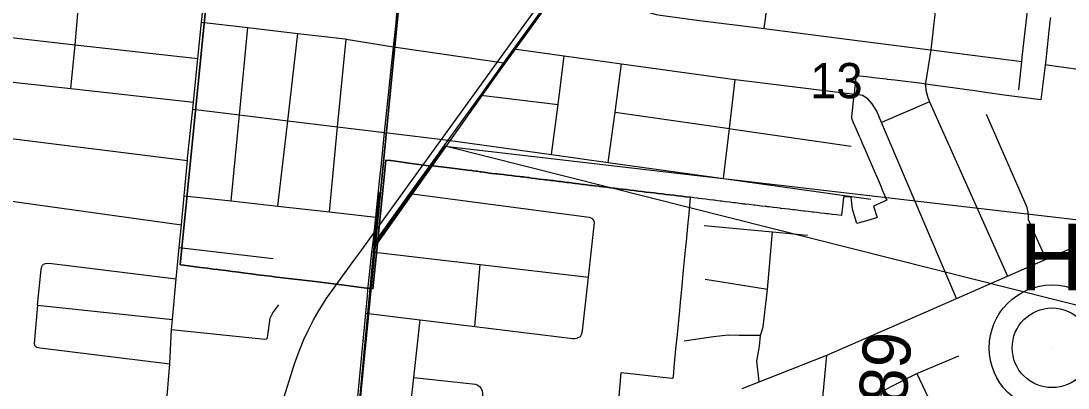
# Model space of a CAD drawing. Extents: x 0 to 34, y -3.9 to 26.2.
# Drawn here: x 5.478 to 6.718, y 17.116 to 17.55 of the extents above; entities that cross this region are included whole.
import ezdxf

# ---------------------------------------------------------------- set-up
doc = ezdxf.new("R2010")
doc.units = 0
for name, color, linetype in [('GM_X_City_Street', 7, 'Continuous'), ('GM_X_Corporation', 7, 'Continuous'), ('GM_X_County_Road', 7, 'Continuous'), ('GM_X_County_Road_Text', 7, 'Continuous'), ('GM_X_Rail_Line', 7, 'Continuous'), ('GM_X_Section', 7, 'Continuous'), ('GM_X_Section_Text', 7, 'Continuous'), ('GM_X_State_Route', 7, 'Continuous'), ('GM_X_Township_Road', 7, 'Continuous'), ('GM_X_Unincorporated', 7, 'Continuous'), ('GM_X_Unincorporated_Location', 7, 'Continuous'), ('GM_X_Unincorporated_Text', 7, 'Continuous'), ('GM_X_US_Route', 7, 'Continuous'), ('SH_Text', 7, 'Continuous')]:
    doc.layers.add(name, color=color, linetype=linetype)

msp = doc.modelspace()

# ---------------------------------------------------------------- linework, layer by layer
at = {"layer": 'GM_X_City_Street'}
for p, q in [((6.0224, 17.4626), (6.1139, 17.4515)), ((5.6654, 17.282), (5.7766, 17.2692)), ((6.0155, 17.1885), (6.0217, 17.262)), ((5.4976, 17.2137), (5.6574, 17.1968))]:
    msp.add_line(p, q, dxfattribs=at)
for points in [[(6.3581, 17.5413), (6.367, 17.6089), (6.3745, 17.666), (6.3821, 17.7239)], [(6.6593, 17.4687), (6.663, 17.5023), (6.6636, 17.5075), (6.6701, 17.5656), (6.6704, 17.569), (6.6767, 17.6249), (6.6834, 17.6857), (6.6862, 17.7111)], [(6.549, 17.4743), (6.5555, 17.5161), (6.5632, 17.5831), (6.5696, 17.6395), (6.5764, 17.6991)], [(6.1086, 17.5816), (6.1848, 17.571), (6.1972, 17.568), (6.23, 17.558), (6.2379, 17.5567), (6.2754, 17.5519), (6.3581, 17.5413), (6.4712, 17.5269), (6.5519, 17.5165), (6.5555, 17.5161), (6.663, 17.5023)], [(5.5372, 17.4703), (5.542, 17.5223), (5.5459, 17.5641), (5.5475, 17.5686)], [(5.6971, 16.9593), (5.6819, 16.9939), (5.647, 17.0778), (5.6493, 17.0824), (5.6542, 17.1442), (5.6563, 17.1848), (5.6574, 17.1968), (5.6619, 17.245), (5.6654, 17.282), (5.668, 17.309), (5.6712, 17.3434), (5.6751, 17.3852), (5.6753, 17.3877), (5.6813, 17.4458), (5.6821, 17.4541), (5.6874, 17.5058), (5.6919, 17.549), (5.6925, 17.5555), (5.6935, 17.5648)], [(5.6919, 17.549), (5.7464, 17.5426), (5.8059, 17.5357), (5.8617, 17.5292), (5.8629, 17.529), (5.9191, 17.5198), (5.9275, 17.5186), (6.0498, 17.5008)], [(5.4246, 17.5356), (5.542, 17.5223), (5.6874, 17.5058)], [(5.727, 17.3372), (5.7366, 17.4391), (5.7464, 17.5426)], [(5.7823, 17.331), (5.794, 17.4321), (5.8059, 17.5357)], [(5.8433, 17.3242), (5.8529, 17.425), (5.8629, 17.529)], [(6.0617, 17.5173), (6.1213, 17.509), (6.1892, 17.4997), (6.3237, 17.4811), (6.327, 17.4807), (6.4649, 17.4638)], [(6.1063, 17.3921), (6.1139, 17.4515), (6.1213, 17.509)], [(6.1732, 17.3827), (6.1814, 17.4425), (6.1892, 17.4997)], [(5.4395, 17.4812), (5.5372, 17.4703), (5.6821, 17.4541)], [(6.3099, 17.3637), (6.3169, 17.423), (6.3237, 17.4811)], [(5.6813, 17.4458), (5.7366, 17.4391), (5.794, 17.4321), (5.8529, 17.425), (5.9085, 17.4182), (5.9125, 17.4178), (5.9838, 17.4091), (6.1063, 17.3921), (6.1732, 17.3827), (6.3099, 17.3637), (6.4842, 17.3394)], [(6.1814, 17.4425), (6.3169, 17.423), (6.3211, 17.4224), (6.4608, 17.4023)], [(5.4401, 17.3772), (5.4428, 17.4045), (5.4444, 17.407), (5.4464, 17.4092), (5.4488, 17.4101), (5.4528, 17.4111), (5.4567, 17.412), (5.46, 17.4118), (5.6751, 17.3852)], [(5.4401, 17.3772), (5.4389, 17.3468), (5.4393, 17.3451), (5.4401, 17.3443), (5.4433, 17.3427), (5.4506, 17.3402), (5.4612, 17.3377), (5.668, 17.309)], [(5.9384, 17.3461), (6.1506, 17.3179), (6.154, 17.3167)], [(5.6712, 17.3434), (5.727, 17.3372), (5.7823, 17.331), (5.8433, 17.3242), (5.898, 17.3181)], [(6.1404, 17.1765), (6.1418, 17.1792), (6.1428, 17.1833), (6.1498, 17.2469), (6.1569, 17.3117), (6.1563, 17.3141), (6.1554, 17.3154), (6.154, 17.3167)], [(5.8936, 17.277), (6.0217, 17.262), (6.1498, 17.2469)], [(5.4976, 17.2137), (5.5017, 17.2561), (5.5027, 17.2597), (5.5035, 17.2612), (5.5048, 17.2625), (5.507, 17.2632), (5.5098, 17.2634), (5.5147, 17.2631), (5.6619, 17.245)], [(5.4976, 17.2137), (5.4937, 17.1682), (5.4941, 17.1665), (5.4954, 17.1649), (5.4968, 17.1642), (5.5004, 17.1633), (5.5037, 17.1627), (5.6542, 17.1442)], [(5.6563, 17.1848), (5.7669, 17.1737), (5.7685, 17.1739), (5.7692, 17.1741), (5.7697, 17.1746), (5.77, 17.1754), (5.7704, 17.1779), (5.7729, 17.1983), (5.7761, 17.2047), (5.7834, 17.2141)], [(5.8862, 17.2044), (5.9472, 17.1969), (5.9508, 17.1965), (6.0155, 17.1885), (6.1314, 17.1743), (6.1336, 17.1743), (6.1368, 17.175), (6.1404, 17.1765)], [(5.9329, 17.0358), (5.9332, 17.0387), (5.9432, 17.1282), (5.9508, 17.1965)], [(5.9432, 17.1282), (6.0162, 17.1201), (6.0188, 17.1189), (6.0207, 17.1174), (6.023, 17.1151), (6.0241, 17.1123), (6.0246, 17.1089), (6.0243, 17.1052), (6.0187, 17.0469)]]:
    msp.add_lwpolyline(points, dxfattribs=at)
at = {"layer": 'GM_X_Corporation'}
for points in [[(5.6984, 17.5835), (5.6666, 17.2614), (5.6707, 17.261), (5.6731, 17.2607), (5.6907, 17.2585), (5.6983, 17.2575), (5.7057, 17.2566), (5.711, 17.2559), (5.7133, 17.2556), (5.7207, 17.2547), (5.7283, 17.2537), (5.7358, 17.2527), (5.7433, 17.2518), (5.7508, 17.2508), (5.7584, 17.2499), (5.7614, 17.2495), (5.7658, 17.2489), (5.7734, 17.248), (5.7779, 17.2474), (5.7808, 17.2471), (5.7984, 17.245), (5.8264, 17.2418), (5.8447, 17.2394), (5.8576, 17.2379), (5.8869, 17.2341), (5.8885, 17.2339), (5.8944, 17.2332), (5.8992, 17.2785), (5.9101, 17.3857), (5.9149, 17.3851), (5.9158, 17.385), (5.9431, 17.3811), (5.9463, 17.3806), (5.9491, 17.3803), (5.9577, 17.3792), (5.9605, 17.3789), (5.9688, 17.3784), (5.9854, 17.3764), (5.9947, 17.3752), (6.0041, 17.374), (6.0071, 17.3737), (6.0119, 17.3731), (6.0135, 17.3729), (6.0165, 17.3725), (6.0187, 17.3723), (6.0212, 17.3719), (6.023, 17.3717), (6.026, 17.3712), (6.0307, 17.3704), (6.0323, 17.3703), (6.0354, 17.3699), (6.0401, 17.3694), (6.0418, 17.3692), (6.0447, 17.3689), (6.0495, 17.3684), (6.0512, 17.3682), (6.0539, 17.3679), (6.0587, 17.3673), (6.0606, 17.3671), (6.0636, 17.3667), (6.0682, 17.3661), (6.0699, 17.3659), (6.0728, 17.3656), (6.0775, 17.365), (6.0793, 17.3648), (6.082, 17.3644), (6.0869, 17.3638), (6.0887, 17.3636), (6.0916, 17.3632), (6.0963, 17.3627), (6.0982, 17.3624), (6.1009, 17.3621), (6.1056, 17.3615), (6.1076, 17.3613), (6.1104, 17.3609), (6.115, 17.3604), (6.117, 17.3602), (6.1197, 17.3598), (6.1243, 17.3592), (6.1265, 17.359), (6.1293, 17.3586), (6.1315, 17.3584), (6.134, 17.358), (6.1358, 17.3578), (6.1384, 17.3575), (6.1432, 17.3569), (6.1452, 17.3567), (6.148, 17.3563), (6.1526, 17.3557), (6.1546, 17.3555), (6.1573, 17.3552), (6.162, 17.3546), (6.1628, 17.3545), (6.1669, 17.354), (6.1713, 17.3534), (6.1738, 17.3531), (6.176, 17.3529), (6.1808, 17.3523), (6.1837, 17.3519), (6.1854, 17.3517), (6.1901, 17.3511), (6.1948, 17.3506), (6.1994, 17.35), (6.2041, 17.3495), (6.2089, 17.3489), (6.2135, 17.3484), (6.2182, 17.3478), (6.2229, 17.3473), (6.2277, 17.3467), (6.2323, 17.3461), (6.237, 17.3456), (6.2417, 17.345), (6.2464, 17.3445), (6.2511, 17.3439), (6.2558, 17.3433), (6.2604, 17.3428), (6.2651, 17.3422), (6.2699, 17.3417), (6.2705, 17.3416), (6.2682, 17.3175), (6.268, 17.3154), (6.2659, 17.2943), (6.2658, 17.2931), (6.2645, 17.279), (6.2622, 17.2553), (6.2599, 17.2323), (6.2585, 17.2174), (6.2575, 17.2074), (6.2544, 17.1751), (6.2535, 17.1659), (6.251, 17.1404), (6.2504, 17.1336), (6.2497, 17.127), (6.2416, 17.1278), (6.2207, 17.1302), (6.2069, 17.1317), (6.1881, 17.1338), (6.1833, 17.0778)], [(6.6968, 17.5547), (6.6962, 17.5496), (6.6958, 17.5453), (6.6954, 17.542), (6.6951, 17.539), (6.6947, 17.5352), (6.6946, 17.5348), (6.6938, 17.5272), (6.693, 17.5195), (6.6921, 17.512), (6.6913, 17.5041), (6.6902, 17.4948), (6.689, 17.4853), (6.6879, 17.4759), (6.6868, 17.4666), (6.6856, 17.4569), (6.6639, 17.4598), (6.6544, 17.461), (6.6422, 17.4626), (6.6254, 17.465), (6.6046, 17.468), (6.601, 17.4685), (6.5815, 17.4711), (6.5546, 17.4746), (6.5447, 17.4763), (6.5127, 17.4801), (6.5041, 17.4811), (6.5029, 17.4813), (6.487, 17.4831), (6.4854, 17.4833), (6.4751, 17.4846), (6.4666, 17.4856), (6.4664, 17.4856), (6.4663, 17.4844), (6.4647, 17.4684), (6.4647, 17.4682), (6.4637, 17.4588), (6.4615, 17.4373), (6.4613, 17.4352), (6.4635, 17.4303), (6.467, 17.4221), (6.4705, 17.4139), (6.4722, 17.4099), (6.474, 17.4057), (6.4759, 17.4014), (6.4775, 17.3976), (6.481, 17.3894), (6.4846, 17.3812), (6.4881, 17.373), (6.4882, 17.3727), (6.4916, 17.3649), (6.4951, 17.3567), (6.4986, 17.3486), (6.4986, 17.3485), (6.4994, 17.3468), (6.5025, 17.3395), (6.5031, 17.3381), (6.4874, 17.3311), (6.4874, 17.3309), (6.4917, 17.3175), (6.4807, 17.3142), (6.4732, 17.312), (6.4676, 17.3104), (6.4626, 17.3274), (6.4611, 17.3416), (6.4519, 17.3421), (6.4517, 17.3421), (6.4505, 17.3298), (6.4496, 17.3211), (6.4495, 17.32), (6.4436, 17.3207), (6.4389, 17.3213), (6.4341, 17.3218), (6.4319, 17.3221), (6.4295, 17.3224), (6.4248, 17.3229), (6.4201, 17.3235), (6.4165, 17.3239), (6.4153, 17.3241), (6.4146, 17.3241), (6.4106, 17.3246), (6.4061, 17.3252), (6.4049, 17.3253), (6.4013, 17.3257), (6.3965, 17.3262), (6.394, 17.3265), (6.3918, 17.3268), (6.3871, 17.3273), (6.3825, 17.3279), (6.3777, 17.3284), (6.377, 17.3285), (6.3732, 17.329), (6.3685, 17.3295), (6.3639, 17.3301), (6.3619, 17.3303), (6.3609, 17.3305), (6.359, 17.3306), (6.3543, 17.3312), (6.3498, 17.3317), (6.3464, 17.3322), (6.3452, 17.3323), (6.3402, 17.3329), (6.3357, 17.3334), (6.3339, 17.3336), (6.3326, 17.3338), (6.331, 17.3339), (6.3262, 17.3345), (6.3237, 17.3348), (6.3216, 17.3351), (6.3194, 17.3354), (6.3168, 17.3357), (6.3122, 17.3363), (6.3074, 17.3369), (6.3058, 17.3371), (6.3028, 17.3375), (6.3008, 17.3377), (6.2989, 17.338), (6.2981, 17.3381), (6.2932, 17.3387), (6.2888, 17.3393), (6.284, 17.3399), (6.2803, 17.3403), (6.2793, 17.3405), (6.2746, 17.3411), (6.2731, 17.3413), (6.2705, 17.3416), (6.2699, 17.3417), (6.2651, 17.3422), (6.2604, 17.3428), (6.2558, 17.3433), (6.2511, 17.3439), (6.2464, 17.3445), (6.2417, 17.345), (6.237, 17.3456), (6.2323, 17.3461), (6.2277, 17.3467), (6.2229, 17.3473), (6.2182, 17.3478), (6.2135, 17.3484), (6.2089, 17.3489), (6.2041, 17.3495), (6.1994, 17.35), (6.1948, 17.3506), (6.1901, 17.3511), (6.1854, 17.3517), (6.1837, 17.3519), (6.1808, 17.3523), (6.176, 17.3529), (6.1738, 17.3531), (6.1713, 17.3534), (6.1669, 17.354), (6.1628, 17.3545), (6.162, 17.3546), (6.1573, 17.3552), (6.1546, 17.3555), (6.1526, 17.3557), (6.148, 17.3563), (6.1452, 17.3567), (6.1432, 17.3569), (6.1384, 17.3575), (6.1358, 17.3578), (6.134, 17.358), (6.1293, 17.3586), (6.1265, 17.359), (6.1243, 17.3592), (6.1197, 17.3598), (6.117, 17.3602), (6.115, 17.3604), (6.1104, 17.3609), (6.1076, 17.3613), (6.1056, 17.3615), (6.1009, 17.3621), (6.0982, 17.3624), (6.0963, 17.3627), (6.0916, 17.3632), (6.0887, 17.3636), (6.0869, 17.3638), (6.082, 17.3644), (6.0793, 17.3648), (6.0775, 17.365), (6.0728, 17.3656), (6.0699, 17.3659), (6.0682, 17.3661), (6.0636, 17.3667), (6.0606, 17.3671), (6.0587, 17.3673), (6.0539, 17.3679), (6.0512, 17.3682), (6.0495, 17.3684), (6.0447, 17.3689), (6.0418, 17.3692), (6.0401, 17.3694), (6.0354, 17.3699), (6.0323, 17.3703), (6.0307, 17.3704), (6.026, 17.3712), (6.023, 17.3717), (6.0212, 17.3719), (6.0187, 17.3723), (6.0165, 17.3725), (6.0135, 17.3729), (6.0119, 17.3731), (6.0071, 17.3737), (6.0041, 17.374), (5.9947, 17.3752), (5.9854, 17.3764), (5.9688, 17.3784), (5.9605, 17.3789), (5.9577, 17.3792), (5.9491, 17.3803), (5.9463, 17.3806), (5.9431, 17.3811), (5.9158, 17.385), (5.9149, 17.3851), (5.9101, 17.3857), (5.8992, 17.2785), (5.8944, 17.2332), (5.8885, 17.2339), (5.8869, 17.2341), (5.8576, 17.2379), (5.8447, 17.2394), (5.8264, 17.2418), (5.7984, 17.245), (5.7808, 17.2471), (5.7779, 17.2474), (5.7734, 17.248), (5.7658, 17.2489), (5.7614, 17.2495), (5.7584, 17.2499), (5.7508, 17.2508), (5.7433, 17.2518), (5.7358, 17.2527), (5.7283, 17.2537), (5.7207, 17.2547), (5.7133, 17.2556), (5.711, 17.2559), (5.7057, 17.2566), (5.6983, 17.2575), (5.6907, 17.2585), (5.6731, 17.2607), (5.6707, 17.261), (5.6666, 17.2614), (5.6984, 17.5835)]]:
    msp.add_lwpolyline(points, dxfattribs=at)
at = {"layer": 'GM_X_County_Road'}
for p, q in [((5.9033, 17.3679), (5.9044, 17.3782)), ((5.8888, 17.232), (5.8907, 17.25))]:
    msp.add_line(p, q, dxfattribs=at)
for points in [[(5.9611, 17.3776), (5.9838, 17.4091), (6.0224, 17.4626), (6.0498, 17.5008), (6.0617, 17.5173), (6.0891, 17.5554), (6.092, 17.5592), (6.1086, 17.5816), (6.1353, 17.6176), (6.15, 17.6374), (6.1899, 17.6911), (6.2298, 17.7449), (6.2477, 17.769), (6.2727, 17.8042), (6.3205, 17.8715), (6.3384, 17.8967), (6.3681, 17.9385), (6.3863, 17.9689), (6.3919, 17.9797), (6.4065, 18.0098), (6.4369, 18.0771), (6.4449, 18.0964), (6.4488, 18.1059)], [(5.9044, 17.3782), (5.9051, 17.3854), (5.9085, 17.4182), (5.9191, 17.5198), (5.9217, 17.5443), (5.9242, 17.5725), (5.9254, 17.5848), (5.9312, 17.6448), (5.9371, 17.7057), (5.9508, 17.8482), (5.9549, 17.8904), (5.9608, 17.9517), (5.9664, 18.0102), (5.977, 18.069)], [(5.8945, 17.285), (5.9384, 17.3461), (5.9611, 17.3776)], [(5.8907, 17.25), (5.8936, 17.277), (5.8945, 17.285), (5.898, 17.3181), (5.9026, 17.3607), (5.9033, 17.3679)], [(5.8742, 17.0308), (5.8715, 17.0472), (5.8862, 17.2044), (5.8881, 17.2248), (5.8888, 17.232)], [(6.4167, 16.9806), (6.4268, 17.0956), (6.4322, 17.1547)]]:
    msp.add_lwpolyline(points, dxfattribs=at)
at = {"layer": 'GM_X_Rail_Line'}
for points in [[(5.7241, 16.9743), (5.8452, 17.029), (5.873, 17.0335), (5.8979, 17.2837), (6.0426, 17.4881), (6.3175, 17.8683), (6.3835, 17.9611), (6.4086, 18.0098), (6.517, 18.2722), (6.6945, 18.7013), (6.8945, 19.188), (6.9673, 19.2641), (7.0598, 19.3383), (7.1575, 19.4128), (7.1736, 19.4378), (7.1863, 19.6097), (7.204, 19.7377)], [(5.7871, 17.0976), (5.8019, 17.1442), (5.8074, 17.1592), (5.813, 17.1733), (5.8179, 17.1839), (5.8242, 17.1963), (5.8298, 17.2058), (5.8392, 17.2212), (5.8585, 17.2481), (5.8733, 17.2684), (5.8814, 17.2793), (5.9223, 17.3359), (6.0705, 17.5409), (6.185, 17.6987)]]:
    msp.add_lwpolyline(points, dxfattribs=at)
at = {"layer": 'GM_X_Section'}
for points in [[(4.9898, 18.1753), (5.9742, 18.0677), (5.8743, 17.0495), (4.8928, 17.1679)], [(5.9742, 18.0677), (7.0185, 17.9275), (6.9147, 16.9222), (5.8743, 17.0495)]]:
    msp.add_lwpolyline(points, close=True, dxfattribs=at)
at = {"layer": 'GM_X_State_Route'}
for p, q in [((6.6462, 17.2481), (6.692, 17.2682)), ((6.5857, 17.2217), (6.6462, 17.2481)), ((6.5496, 17.2059), (6.5857, 17.2217)), ((6.4322, 17.1547), (6.5496, 17.2059)), ((6.374, 17.1317), (6.4322, 17.1547)), ((6.3317, 17.115), (6.3522, 17.1231)), ((6.3522, 17.1231), (6.374, 17.1317))]:
    msp.add_line(p, q, dxfattribs=at)
msp.add_lwpolyline([(6.692, 17.2682), (6.8824, 17.3515), (6.9643, 17.3874)], dxfattribs=at)
at = {"layer": 'GM_X_Township_Road'}
for p, q in [((6.5536, 17.4548), (6.4968, 17.4303)), ((6.3618, 17.2325), (6.2881, 17.244)), ((6.5385, 17.1327), (6.5586, 17.0911))]:
    msp.add_line(p, q, dxfattribs=at)
for points in [[(6.9714, 17.4613), (6.8887, 17.4682), (6.7266, 17.4935), (6.6901, 17.4983)], [(6.549, 17.4743), (6.5493, 17.4683), (6.5518, 17.4599), (6.5536, 17.4548), (6.6462, 17.2481)], [(6.5857, 17.2217), (6.4968, 17.4303), (6.4912, 17.4435), (6.4859, 17.4523), (6.4806, 17.4583), (6.4742, 17.4621), (6.4649, 17.4638)], [(6.692, 17.2682), (6.6771, 17.3006), (6.675, 17.3054), (6.6733, 17.3102), (6.6711, 17.3146), (6.6711, 17.3194), (6.6707, 17.3239), (6.6694, 17.3293), (6.6211, 17.4397)], [(6.2867, 17.3082), (6.368, 17.3005), (6.4091, 17.2966)], [(6.3522, 17.1231), (6.3494, 17.1474), (6.3523, 17.1651), (6.3535, 17.1778), (6.3566, 17.1882), (6.3618, 17.2325), (6.368, 17.3005)], [(6.3535, 17.1778), (6.3282, 17.1779), (6.3153, 17.1783), (6.2979, 17.1761), (6.2632, 17.1713)], [(6.4925, 17.0864), (6.4938, 17.1), (6.4956, 17.1056), (6.4982, 17.1103), (6.5, 17.1121), (6.5024, 17.1143), (6.5098, 17.1183), (6.5385, 17.1327), (6.5883, 17.1539)]]:
    msp.add_lwpolyline(points, dxfattribs=at)
at = {"layer": 'GM_X_Unincorporated'}
for radius in [0.0744, 0.0472]:
    msp.add_circle((6.6988, 17.1633), radius, dxfattribs=at)
at = {"layer": 'GM_X_Unincorporated_Location'}
msp.add_line((6.6988, 17.1633), (6.6988, 17.1633), dxfattribs=at)
at = {"layer": 'GM_X_US_Route'}
for p, q in [((6.6462, 17.2481), (6.692, 17.2682)), ((6.5857, 17.2217), (6.6462, 17.2481)), ((6.5496, 17.2059), (6.5857, 17.2217)), ((6.4322, 17.1547), (6.5496, 17.2059)), ((6.374, 17.1317), (6.4322, 17.1547)), ((6.3317, 17.115), (6.3522, 17.1231)), ((6.3522, 17.1231), (6.374, 17.1317))]:
    msp.add_line(p, q, dxfattribs=at)
msp.add_lwpolyline([(6.692, 17.2682), (6.8824, 17.3515), (6.9643, 17.3874)], dxfattribs=at)
at = {"layer": 'SH_Text'}
msp.add_line((5.896, 17.2839), (5.9021, 17.3473), dxfattribs=at)
msp.add_lwpolyline([(5.8726, 17.0315), (5.896, 17.2839), (5.9803, 17.4022)], dxfattribs=at)
msp.add_lwpolyline([(9.5912, 16.9819), (9.5912, 16.4915), (5.9803, 17.4022)], close=True, dxfattribs=at)

# ---------------------------------------------------------------- texts
at = {"layer": 'GM_X_County_Road_Text'}
msp.add_text('C-289', height=0.05682, rotation=85.3275, dxfattribs=at).set_placement((6.5161, 16.9733))
at = {"layer": 'GM_X_Section_Text'}
msp.add_text('13', height=0.04186, rotation=0, dxfattribs=at).set_placement((6.4123, 17.4588))
at = {"layer": 'GM_X_Unincorporated_Text'}
msp.add_text('Harewood Acres', height=0.078977, rotation=0, dxfattribs=at).set_placement((6.6602, 17.2312))

doc.saveas('drawing.dxf')
